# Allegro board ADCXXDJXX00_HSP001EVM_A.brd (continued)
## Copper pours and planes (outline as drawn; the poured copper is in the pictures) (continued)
VDDL19 on L04_SIG-1: 40.48,29.87 40.48,17.34 54.77,17.34 54.84,17.41 54.84,29.87 54.4,30.32 40.95,30.32 40.51,29.87
VDDL19 on L08_PWR-2: 52.58,48.13 52.58,52.07 54.1,53.59 74.04,53.59 74.68,52.96 74.68,26.16 73.78,25.27 52.07,25.27 50.55,26.8 50.55,37.21 49.53,38.23 49.53,45.09 ; 13 cut-outs
VDDL19 on L10_SIG-2: 72.78,48.61 72.78,46.71 74.06,46.71 74.06,48.61
VINA on TOP (solid shape): 5.13,86.18 5.24,86.12 5.38,86.12 5.38,85.84 5.24,85.84 5.13,85.78 5.08,85.66 2.29,85.66 2.29,86.3 5.08,86.3
VINB on TOP (solid shape): 5.13,60.78 5.24,60.72 5.38,60.72 5.38,60.44 5.24,60.44 5.13,60.38 5.08,60.26 2.29,60.26 2.29,60.9 5.08,60.9
1P4V on TOP: 50.94,13.04 50.94,9.62 53.04,9.62 53.04,13.04
1P4V on BOTTOM: 53.92,6.07 53.92,12.94 53.88,12.94 53.37,13.45 50.68,13.45 50.22,12.98 50.22,6.03 50.53,5.72 53.58,5.72
1P4V on L06_PWR-1: 52.05,13.04 52.05,6.31 53.07,6.31 53.07,13.04
1P8V_USB on BOTTOM: 62.48,41.03 62.48,42.93 59.94,42.93 59.94,43.21 58.05,43.21 58.05,42.93 54.48,42.93 54.48,46.74 63.75,46.74 63.75,43.05 66.67,43.05 66.67,37.08 63.13,37.08 63.13,41.03
1P8V_USB on L10_SIG-2: 64.94,46.74 66.72,44.96 66.72,36.77 65.46,35.52 51.66,35.52 49.36,37.82 49.36,45.95 50.14,46.74 ; 12 cut-outs
2P2V on TOP: 36.29,13.88 36.29,10.28 38.79,10.28 38.79,13.88
2P2V on BOTTOM: 36.31,13.72 36.31,10.21 36.94,9.58 37.05,9.58 37.66,8.98 37.66,7.17 38.19,6.63 40.33,6.63 40.45,6.75 40.45,12.07 38.79,13.72
12P0V_RX on TOP: 140.11,45.68 140.11,42.22 141.41,42.22 141.41,45.68
BYPASS on BOTTOM: 68.56,14.86 68.56,13.52 70.77,13.52 71.8,12.48 71.8,8.88 72.25,8.44 74.8,8.44 75.78,9.41 75.78,13.86 75.61,14.02 73.55,14.02 72.71,14.86
DEVCLKIN on TOP (solid shape): 5.13,73.48 5.24,73.42 5.38,73.42 5.38,73.14 5.24,73.14 5.13,73.08 5.08,72.96 2.29,72.96 2.29,73.6 5.08,73.6
DEVCLKIN on TOP (solid shape): 15.98,74.17 14.86,74.17 14.74,74.34 14.53,74.41 14.52,74.41 14.52,74.69 14.53,74.69 14.74,74.76 14.86,74.93 15.98,74.93
U19_BYPASS on BOTTOM: 64.26,14.87 64.26,13.57 67.51,13.57 67.51,14.87
V_BUS on BOTTOM: 26.92,18.29 26.92,15.24 30.35,15.24 30.35,18.29
V_BUS on L04_SIG-1: 26.88,18.1 26.88,15.35 30.23,15.35 30.23,18.1
VA11 on BOTTOM: 29.21,82.8 29.21,77.34 34.34,77.34 34.34,81.54 33.1,81.54 32.92,81.72 32.92,82.8
VA11 on BOTTOM: 64.77,15.49 64.77,15.5 72.39,15.5 72.39,19.56 72.26,19.56 72.26,21.34 72.14,21.46 63.37,21.46 63.37,15.62 63.5,15.49
VA11 on L06_PWR-1: 63.37,15.03 63.37,49.07 59.68,52.76 44.79,52.76 43.44,51.42 16.63,51.42 13.71,54.33 13.71,82.3 15.15,83.74 34.05,83.74 39.78,78 39.78,75.68 41.58,73.88 41.58,68.19 42.59,67.18 76.08,67.18 78.36,64.9 78.36,15.03 ; 7 cut-outs
VA19 on BOTTOM: 38.23,14.6 38.23,20.7 36.7,20.7 36.7,24.77 41.53,24.77 41.53,22.79 41.14,22.41 41.14,18.44 41.43,18.16 41.43,16.56 41.67,16.32 43.43,16.32 43.43,14.6
VA19 on BOTTOM: 30.23,68.27 30.23,65.91 33.5,65.91 33.5,68.27
VA19 on L08_PWR-2: 26.67,97.03 24.89,98.81 12.7,98.81 8.38,103.12 8.38,124.33 48.53,124.33 50.58,122.29 50.58,113.7 49.25,112.37 42.83,112.37 40.64,114.55 40.64,117.41 37.28,120.78 23.5,120.78 22.48,119.76 22.48,108.58 24.51,106.55 35.94,106.55 37.72,104.78 37.72,81.41 34.29,77.98 34.29,71.6 33.66,70.97 33.66,68.71 35.31,67.06 35.31,41.78 35.43,41.66 35.43,36.45 41.91,29.97 41.91,20.95 42.93,19.94 42.93,15.18 42.16,14.41 28.05,14.41 26.67,15.79 ; 3 cut-outs
VADJ_RX on TOP: 115.83,33.8 115.83,31.44 132.19,31.44 134.53,33.78 142.99,33.78 148.42,39.22 148.42,86.34 147.27,87.49 144.52,87.49 142.13,89.89 137.29,89.89 137.11,89.71 137.11,88.91 137.29,88.73 139.63,88.73 142.5,85.86 144.49,85.86 145.78,84.58 145.78,80.36 146.65,79.49 146.65,41.83 140.19,35.37 137.02,35.37 135.9,36.5 135.9,37.87 134.43,39.34 133.56,39.34 132.85,38.62 132.85,37.05 129.6,33.8
VADJ_RX on L10_SIG-2: 132.22,40.72 132.22,37.48 140.29,37.48 140.29,40.72
VD11 on BOTTOM: 72.9,20.19 72.9,15.75 76.03,15.75 76.03,11.6 76.33,11.3 79.12,11.3 79.63,11.81 79.63,14.73 78.61,15.75 78.61,20.7 76.71,20.7 76.2,20.19
VD11 on L06_PWR-1: 47.09,102.87 47.09,105.85 46.87,106.07 32.73,106.07 32.43,105.77 32.43,85.99 39.98,78.45 39.98,76.58 40.5,76.05 40.99,76.05 41.55,76.62 41.55,94.67 38.54,97.68 38.54,100.92 41.23,103.6 44.22,103.6 44.96,102.87
VD11 on L08_PWR-2: 36.7,66.22 34.21,68.71 34.21,71.42 34.42,71.63 34.44,71.63 34.8,71.98 34.8,76.93 38.43,80.56 48.03,80.56 51.17,77.42 51.17,47.13 48.39,44.35 48.39,38.48 50.04,36.83 50.04,26.8 52.2,24.64 76.83,24.64 78.61,22.86 78.61,17.14 79.76,16 79.76,11.81 78.49,10.54 73.15,10.54 71.99,11.71 65.26,11.71 64.57,12.4 64.57,14.9 63.86,15.61 47.84,15.61 42.67,20.78 42.67,30.23 36.7,36.2
VD11 on L10_SIG-2: 35.57,49.26 35.57,45.87 36.17,45.26 40.02,45.26 44.34,49.58 44.34,56.16 41.46,59.04 33.23,59.04 24.12,49.93 24.12,27.43 37.73,13.82 73.19,13.82 75.78,11.24 79.86,11.24 81.65,13.03 81.65,18.41 77.21,22.84 46.66,22.84 31.94,37.56 31.94,47.7 33.5,49.26 ; 1 cut-out
VIO_B_M2C_RX on TOP: 130.8,37.08 132.47,37.08 132.47,38.83 133.5,39.85 133.5,40.68 131.19,40.68 130.8,40.29
VPHY on BOTTOM: 52.75,42.54 52.95,42.34 52.95,41.39 53.13,41.21 54.85,41.21 54.95,41.31 54.95,42.26 54.79,42.42 54.16,42.42 54.02,42.56 54.02,43.52 53.9,43.64 52.78,43.64 52.75,43.61
N19884870 on TOP: 75.7,104.85 78.44,104.85 79.58,105.99 79.58,110.51 78.14,111.96 75.53,111.96 74.84,111.27 74.84,105.71
N19884870 on BOTTOM: 77.95,110.43 76.18,110.43 76.18,108.17 76.81,108.17 76.84,108.15 76.84,105 78.59,105 78.59,107.79 77.95,108.43
N19887756 on TOP: 91.42,104.46 91.42,100.91 91.29,100.78 90.15,100.78 90.15,104.46
N19887756 on TOP: 91.8,105.23 91.8,107.89 91.67,107.89 91.67,107.77 90.27,107.77 90.27,111.58 91.67,111.58 91.67,108.91 92.56,108.91 92.56,105.23
N19887756 on L10_SIG-2: 90.02,102.69 90.02,111.58 92.81,111.58 92.81,102.69
N19887760 on TOP: 94.78,108.02 94.78,106.87 96.67,106.87 96.67,108.38 95.14,108.38
N19887762 on TOP: 101.32,109.1 101.32,106.9 102.19,106.9 102.19,109.1
N19887836 on TOP: 91.82,100.53 91.82,97.95 93.77,97.95 93.77,100.53
N19887836 on L10_SIG-2: 91.27,97.23 91.27,101.21 93.7,101.21 93.7,98.62 102.08,98.62 102.08,102.18 104.75,102.18 104.75,97.23
N19887910 on TOP: 99.21,98.31 99.21,96.13 100.41,96.13 100.41,98.31
N19887912 on TOP: 101.48,98.26 101.48,96.26 102.75,96.26 102.75,98.26
N19887930 on TOP: 95.75,98.26 95.75,96.14 97.83,96.14 97.83,98.26
N20392160 on TOP: 17.49,15.21 17.49,16.35 15.95,16.35 15.45,16.86 14.07,16.86 13.81,16.61 13.81,15.47 14.08,15.21
N20392160 on BOTTOM: 7.25,23.41 7.25,18.49 10.27,15.47 15.3,15.47 15.49,15.67 15.49,21.15 12.69,23.96 7.79,23.96
N20399374 on BOTTOM, L08_PWR-2: 69.85,8.13 69.85,9.52 68.33,9.52 68.33,10.67 71.25,10.67 71.25,8.13
N20560674 on TOP: 138.64,44.05 137.79,44.05 137.17,43.43 137.17,38.22 138.3,37.09 139.91,37.09 140.96,38.14 140.96,40.91 140.84,41.04 140.28,41.04 139.74,41.58 139.74,43.97 139.46,44.25 138.85,44.25

Small or netless copper shapes (teardrops, artwork), in the pictures only: 2 on TOP, 6 on L11_GND-6

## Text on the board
BOTTOM: LAYER 12 (BOTTOM SIDE)
Board Geometry/Soldermask Bottom: SOLDERMASK BOTTOM
Ref Des/Silkscreen Bottom: G | GND | LMX2582 | LMK04828 | SILKSCREEN BOTTOM
User.Comments: TEXAS INSTRUMENTS, INC. | ADCXXDJXX00EVM REV A | HSP-001 | SEE NOTE 16 | THIS BOARD IS FOR THE FOLLOWING DEVICES: | ADC08DJ2700, ADC08DJ3200, ADC12DJ1600, ADC12DJ2700, ADC12DJ3200
TOP: LAYER 1 (TOP SIDE)
Board Geometry/Soldermask Top: SOLDERMASK TOP
Ref Des/Silkscreen Top: PRSNT_M2C_L | ADCXXDJXX00 | ROHS EXEMPT | TDI | TDO | HSP-001 | SILKSCREEN TOP
L02_GND-1: LAYER 2 - GND
L03_GND-2: LAYER 3 - GND
L04_SIG-1: LAYER 4 - SIG-1
L05_GND-3: LAYER 5 - GND
L06_PWR-1: LAYER 5 - PWR-1
L07_GND-4: LAYER 7 - GND
L08_PWR-2: LAYER 8 - PWR-2
L09_GND-5: LAYER 9 - GND
L10_SIG-2: LAYER 10 - SIG-2
L11_GND-6: LAYER 11 - GND
DIMENSION: PASTEMASK TOP
PLACE_BOUND_TOP: PASTEMASK BOTTOM
ASSEMBLY_DETAIL1: TOP VIEW | SEE NOTE 3 | BOTTOM VIEW
User.6: SOLDERMASK TOP SOCKET BOARD
User.7: PASTEMASK TOP SOCKET BOARD
User.9: FINISH THE HOLE TO 8 MIL | USE 10 MIL DRILL BIT & | TRACE WIDTH | (MILS) | TOL | (%) | SPACING | IMPEDANCE TABLE. | L01_TOP | L04_SIG-1 | L10_SIG-2 | L12_BOTTOM | 50 OHM SINGLE ENDED | 5.5 | 6.5 | 11 | 5 % | 4.9 | 6 | 100 OHM DIFFERENTIAL | TIGHTLY COUPLED | 7.1 | 5 | NIL | 6.3 | 10 | LOOSELY COUPLED | 20.1 | 18 | BACKDRILL SHOULD NOT DISCONNECT THE PAD IN L10_SIG-2
User.14: 11-11-15 | 3. MARK BOARD'S SILKSCREEN WITH THE APPROPRIATE EVM PART NUMBER AND SERIAL NUMBER. | 4. IPC-A-610 / ACCEPTABILITY OF ELECTRONIC ASSEMBLIES, CLASS2, CURRENT REVISION. | HSP-001
User.26: FIGURE | SIZE | 8.0 | 8.01 | 10.0 | 12.0 | 13.0 | 15.0 | 38.0 | 40.0 | 59.0 | 62.0 | 63.0 | 67.0 | 106.0 | 120.0 | 125.0 | 140.0 | 39.0 | 50.0 | DRILL CHART: TOP to BOTTOM | ALL UNITS ARE IN MILS | TOLERANCE | +3.0/-10.0 | +3.0/-3.0 | PLATED | NON-PLATED | QTY | 1712 | 30 | 40 | 122 | 98 | 16 | 8 | 32 | 17 | 24 | 2 | 1
User.27: * | 1 | 3 | A | M | 12 | 7 | 2 | 8 | ABM3 | C
User.29: * | 1
User.34: ADC08DJ3200EVM | ADC12DJ1600EVM | ADC12DJ32OOEVM | ADC08DJ2700EVM | ADC12DJ2700EVM | S/N:
User.36: 2.0 MIL | 6.00 MIL | 2.00 MIL | 5.6 MIL | 5.00 MIL | 7.6  MIL | 4.00 MIL | 3.7 MIL | 3.00 MIL | 7.6 MIL | THIS IS A 12 LAYER BOARD | LAYER STACK-UP | MEGTRON 6 | LAYER 1 TOP | LAYER 2 GND-1 | LAYER 3 GND-2 | LAYER 4 SIG-1 | LAYER 5 GND-3 | LAYER 6 PWR-1 | LAYER 7 GND-4 | LAYER 8 PWR-2 | LAYER 9 GND-5 | LAYER 10 SIG-2 | LAYER 11 GND-6 | LAYER 12 BOTTOM
User.37: NOTES: | - DRILL SIZES LISTED IN LEGEND | ARE CONSIDERED FINISHED. | - VENDOR IS REQUIRED TO SELECT | TOOLING FOR OVERDRILLING. | - LEGEND DOES NOT SPECIFY DEPTH | INTO ADJACENT DIELECTRIC LAYER. | FIGURE | SIZE | 8.01 | BACKDRILL: TOP to L10_SIG-2 | ALL UNITS ARE IN MILS | TOLERANCE | PLATED | QTY | 40
User.42: U2 | Y2 | J20 | J38 | J22 | J5 | J2 | J15 | J14 | J18 | MT1 | J31 | MT2 | R34 | R38 | J6 | J4 | TP28 | R35 | R36 | T2 | R111 | TP13 | TP26 | BALUN1 | BALUN2 | Q1 | TP21 | TP25 | TP12 | U13 | C49 | C52 | R9 | R4 | C45 | C47 | R6 | R1 | TP3 | C76 | D8 | TP31 | R29 | C77 | R179 | R180 | R162 | R151 | TP2 | U6 | TP1 | R41 | R39 | R27 | R28 | R37 | U1 | C209 | U14 | R153 | R152 | TP14 | L3 | TP32 | D1 | C7 | C8 | C5 | C6 | C27 | C26 | C25 | C28 | TP7 | TP10 | TP11 | SJP2 | J7 | TP15 | C207 | JP6 | TP33 | C210 | C208 | U17 | D7 | D5 | D3 | D4 | D6 | U10 | R130 | C215 | C184 | L4 | R160 | R166 | R133 | R134 | R135 | R136 | R137 | C109 | D2 | C114 | C112 | U8 | TP29 | C115 | JP7 | C113 | C118 | TP17 | SJP3 | C107 | U7 | C103 | R115 | R119 | R118 | C117 | C100 | C104 | SJP4 | TP19 | JP5 | R121 | R120 | TP36 | R125 | R124 | TP20 | U9 | R131 | SJP1 | U11 | C246 | R123 | TP27 | R138 | R139 | R140 | R141 | R142 | U12 | R177 | FB6 | C160 | C161 | R176 | R143 | R144 | R145 | R146 | R147 | FB8 | C162 | FB7 | FB2 | R17 | R18 | R11 | R12 | TP24 | TP18 | J23 | JP8 | FB9 | JP9 | FB10 | FB5 | D12 | C235 | TP23 | D11 | TP16 | C154 | FB4 | J24 | R32 | R173 | FB11 | TP22 | C157 | C163 | C164 | C1 | C2 | R99 | U15 | R172 | TP30 | C4 | D10 | R185 | TP4 | R108 | U5 | J28 | J27 | J26 | J30 | C167 | R98 | R97 | R106 | R107 | R104 | R105 | R116 | R117 | R43 | C44 | C46 | J17 | J8 | C11 | J9 | C31 | C12 | C32 | C9 | C29 | C10 | C30 | R150 | C206 | R164 | C185 | R51 | C99 | C211 | R112 | C101 | C105 | R113 | C106 | C102 | R178 | R114 | R174 | R175 | C156 | C155 | C159 | C165 | C158 | R31 | C166 | R170 | C3 | R171 | FB3 | R30 | C14 | R184 | R33 | R96 | D9 | J3 | J1 | TP6 | TP5
User.43: HSP-001 | ADC | DJ   00EVM REV A
User.44: J25 | Y1 | Q3 | C137 | C20 | C134 | C136 | C24 | R73 | R187 | R87 | R90 | R86 | R89 | R128 | R129 | R59 | R60 | R188 | R189 | FB20 | C132 | C233 | C230 | C229 | C131 | C152 | R65 | R64 | R62 | R61 | C234 | U21 | R66 | C249 | U4 | R94 | C226 | C227 | R95 | C228 | FB21 | C237 | C236 | C225 | C250 | R63 | C128 | R22 | R24 | R92 | R84 | C194 | C195 | FB22 | C244 | C242 | C243 | C245 | C193 | U22 | T1 | R69 | C247 | C140 | C248 | C240 | C239 | C130 | C241 | FB1 | C180 | C192 | C238 | R163 | C138 | C139 | C141 | R71 | R168 | C120 | R56 | C172 | R110 | R159 | R46 | C116 | C220 | C179 | U20 | C183 | C221 | C178 | C188 | C108 | R158 | R48 | C187 | C212 | C213 | U3 | C122 | R49 | R167 | R50 | C186 | R122 | C170 | C110 | R47 | R45 | C191 | R44 | R183 | R154 | R155 | R156 | R157 | C111 | R132 | C169 | C171 | R149 | FB12 | C200 | FB13 | R102 | R100 | R101 | R103 | C190 | U16 | C201 | C92 | C93 | C94 | C84 | C43 | R14 | R15 | R16 | R13 | FB16 | C95 | R20 | R23 | C196 | C67 | R19 | R21 | C204 | C205 | C202 | C175 | C83 | C203 | C68 | FB14 | C198 | R42 | R40 | C79 | C80 | C174 | F1 | C42 | C41 | D13 | C48 | C53 | J37 | C36 | C35 | C15 | C34 | C33 | C16 | C18 | C13 | C56 | C65 | C64 | C63 | C62 | C66 | C61 | C54 | C90 | C88 | C86 | C85 | C78 | C57 | C73 | R26 | C89 | C58 | C87 | C82 | C96 | C22 | C91 | R68 | R186 | C143 | R127 | C142 | R126 | R76 | R77 | R81 | R78 | R80 | R79 | R74 | C133 | C146 | R75 | C135 | C145 | C150 | R85 | R93 | R82 | R88 | C144 | C151 | C149 | R83 | C153 | R91 | R57 | R58 | FB23 | R67 | R72 | C224 | R70 | FB19 | C223 | C222 | C217 | FB18 | C216 | R161 | C218 | R165 | R169 | C219 | C214 | C119 | R54 | R55 | C121 | R52 | C176 | C189 | R53 | C168 | C181 | C182 | R109 | FB17 | C38 | C37 | C40 | C39 | C173 | C177 | R148 | R25 | C50 | C51 | C55 | C60 | C69 | C71 | C59 | C70 | C72 | C74 | C21 | C75 | C81 | C19 | C23
